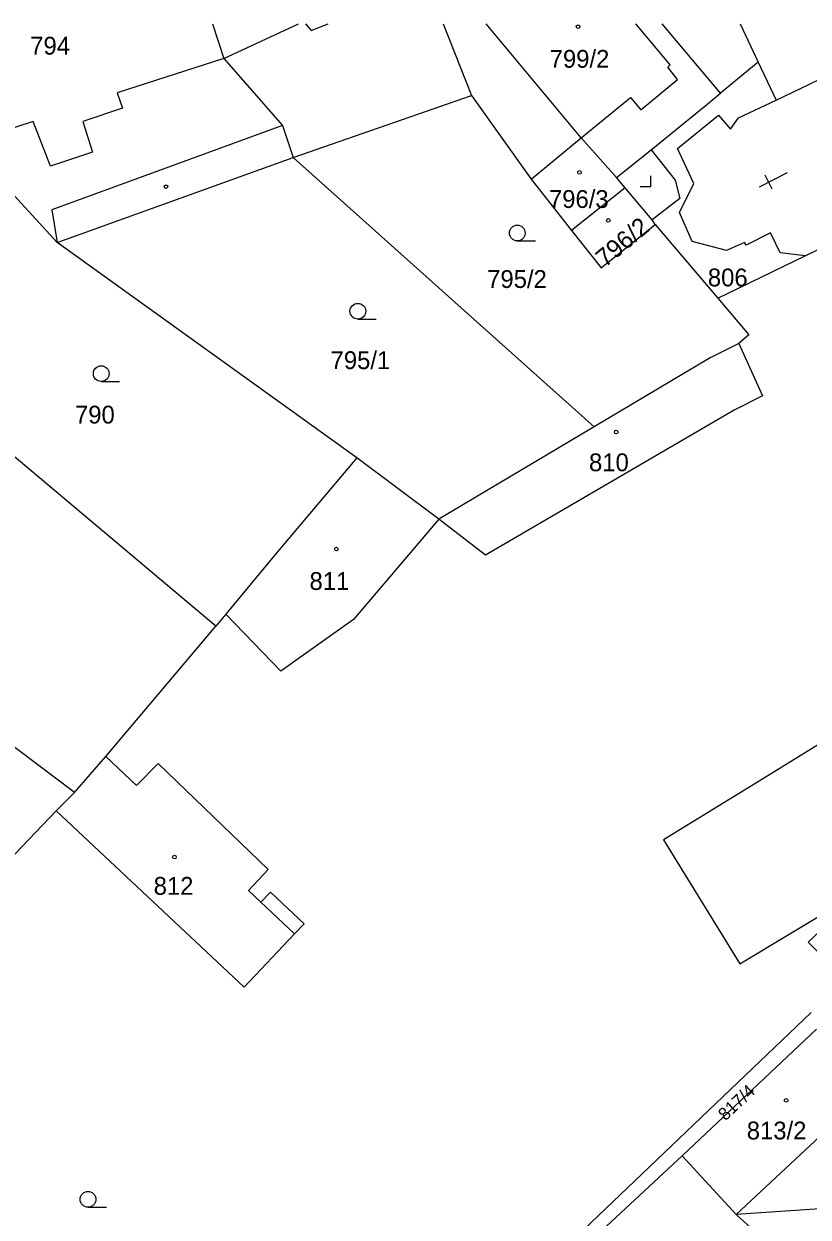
# Model space of a CAD drawing. Extents: x -496682 to -495907, y -1088575 to -1088018.
# Drawn here: x -496396.5 to -496321.7, y -1088133.3 to -1088019.5 of the extents above; entities that cross this region are included whole.
import ezdxf

# ---------------------------------------------------------------- set-up
doc = ezdxf.new("R2010")
doc.units = 0
for name, color, linetype in [('Hranice parcel', 7, 'Continuous'), ('Parcelní čísla', 7, 'Continuous'), ('Vnitřní kresba', 7, 'Continuous'), ('Značky budov', 7, 'Continuous'), ('Značky kultur', 7, 'Continuous')]:
    doc.layers.add(name, color=color, linetype=linetype)

msp = doc.modelspace()

# ---------------------------------------------------------------- linework, layer by layer
at = {"layer": 'Hranice parcel'}
for p, q in [((-496328.16, -1088019.49), (-496326.44, -1088023.13)), ((-496326.44, -1088023.13), (-496330.05, -1088026.09)), ((-496326.44, -1088023.13), (-496324.74, -1088026.75)), ((-496348.1, -1088034.29), (-496343.33, -1088030.37)), ((-496339.97, -1088034.14), (-496343.33, -1088030.37)), ((-496393.29, -1088040.33), (-496370.79, -1088032.22)), ((-496370.79, -1088032.22), (-496342.08, -1088057.91)), ((-496348.1, -1088034.29), (-496344.26, -1088039.18)), ((-496339.12, -1088035.12), (-496339.97, -1088034.14)), ((-496393.29, -1088040.33), (-496398.07, -1088035.13)), ((-496339.12, -1088035.12), (-496344.26, -1088039.18)), ((-496336.28, -1088038.61), (-496330.3, -1088045.65)), ((-496364.73, -1088060.87), (-496393.29, -1088040.33)), ((-496330.3, -1088045.65), (-496321.98, -1088041.61)), ((-496378.15, -1088076.93), (-496400.58, -1088058.06)), ((-496342.08, -1088057.91), (-496356.91, -1088066.71)), ((-496356.91, -1088066.71), (-496364.73, -1088060.87)), ((-496377.22, -1088075.77), (-496378.15, -1088076.93)), ((-496388.65, -1088089.36), (-496378.15, -1088076.93)), ((-496391.63, -1088092.77), (-496388.65, -1088089.36)), ((-496393.38, -1088094.52), (-496391.63, -1088092.77)), ((-496373.06, -1088163.12), (-496321.41, -1088113.75)), ((-496320.9, -1088115.37), (-496333.69, -1088127.43)), ((-496328.55, -1088133.03), (-496315.65, -1088120.99)), ((-496333.69, -1088127.43), (-496357.36, -1088149.42)), ((-496333.69, -1088127.43), (-496328.55, -1088133.03)), ((-496287.5, -1088130.23), (-496328.55, -1088133.03))]:
    msp.add_line(p, q, dxfattribs=at)
for points in [[(-496378.48, -1088019.49), (-496377.39, -1088022.78), (-496371.82, -1088029.18), (-496370.79, -1088032.22)], [(-496343.33, -1088030.37), (-496352.39, -1088019.49)], [(-496330.05, -1088026.09), (-496335.61, -1088019.49)], [(-496324.74, -1088026.75), (-496317.45, -1088023.28), (-496311.34, -1088021.2), (-496307.78, -1088019.49)], [(-496370.79, -1088032.22), (-496353.78, -1088026.33), (-496348.1, -1088034.29)], [(-496339.97, -1088034.14), (-496336.64, -1088031.5), (-496331.54, -1088027.32), (-496330.05, -1088026.09)], [(-496321.98, -1088041.61), (-496324.37, -1088041.31), (-496325.28, -1088039.42), (-496327.61, -1088040.59), (-496327.75, -1088040.32), (-496329.48, -1088041.1), (-496332.73, -1088040.23), (-496333.96, -1088037.46), (-496332.59, -1088034.7), (-496334.13, -1088031.37), (-496330.23, -1088028.2), (-496329.09, -1088029.54), (-496328.32, -1088028.45), (-496324.74, -1088026.75)], [(-496336.28, -1088038.61), (-496336.57, -1088038.17), (-496339.12, -1088035.12)], [(-496321.98, -1088041.61), (-496311.24, -1088036.41), (-496311.47, -1088035.95), (-496310.17, -1088035.32)], [(-496344.26, -1088039.18), (-496341.41, -1088042.74), (-496336.28, -1088038.61)], [(-496330.3, -1088045.65), (-496327.33, -1088049.15), (-496328.29, -1088049.97)], [(-496328.29, -1088049.97), (-496326.03, -1088054.97), (-496328.74, -1088056.34), (-496352.45, -1088070.14), (-496356.91, -1088066.71)], [(-496328.29, -1088049.97), (-496331.02, -1088051.35), (-496342.08, -1088057.91)], [(-496364.73, -1088060.87), (-496372.46, -1088070.06), (-496377.22, -1088075.77)], [(-496391.63, -1088092.77), (-496417.3, -1088073.45), (-496426.74, -1088064.5)], [(-496356.91, -1088066.71), (-496365.03, -1088076.3), (-496371.95, -1088081.22), (-496377.22, -1088075.77)], [(-496309.39, -1088081.23), (-496325.96, -1088091.45), (-496335.48, -1088097.3), (-496328.2, -1088109.13), (-496318.63, -1088103.36)], [(-496388.65, -1088089.36), (-496385.72, -1088092.12), (-496383.67, -1088090.01), (-496373.16, -1088100.13), (-496375.06, -1088102.13), (-496373.87, -1088103.25), (-496372.96, -1088102.28), (-496369.75, -1088105.3), (-496370.66, -1088106.26), (-496375.45, -1088111.36), (-496393.38, -1088094.52)], [(-496419.93, -1088122.62), (-496405.88, -1088107.6), (-496393.38, -1088094.52)], [(-496319.99, -1088105.46), (-496321.7, -1088107.07), (-496318.3, -1088110.48)], [(-496328.55, -1088133.03), (-496327.18, -1088134.28), (-496328.71, -1088135.71)]]:
    msp.add_lwpolyline(points, dxfattribs=at)
at = {"layer": 'Vnitřní kresba'}
for p, q in [((-496377.39, -1088022.78), (-496370.29, -1088019.49)), ((-496369.61, -1088019.49), (-496369.07, -1088020.13)), ((-496369.07, -1088020.13), (-496367.46, -1088019.49)), ((-496356.49, -1088019.49), (-496353.78, -1088026.33)), ((-496334.85, -1088023.38), (-496338.12, -1088019.49)), ((-496377.39, -1088022.78), (-496387.56, -1088026.07)), ((-496335.08, -1088023.62), (-496334.85, -1088023.38)), ((-496334.13, -1088024.78), (-496335.08, -1088023.62)), ((-496337.64, -1088027.69), (-496334.13, -1088024.78)), ((-496387.56, -1088026.07), (-496387.06, -1088027.53)), ((-496343.33, -1088030.37), (-496338.62, -1088026.5)), ((-496338.62, -1088026.5), (-496337.64, -1088027.69)), ((-496387.06, -1088027.53), (-496390.85, -1088028.8)), ((-496395.59, -1088028.81), (-496402.96, -1088031.19)), ((-496393.92, -1088033.06), (-496395.59, -1088028.81)), ((-496390.85, -1088028.8), (-496389.93, -1088031.72)), ((-496371.82, -1088029.18), (-496393.79, -1088037.22)), ((-496389.93, -1088031.72), (-496393.92, -1088033.06)), ((-496336.64, -1088031.5), (-496334.36, -1088034.39)), ((-496334.36, -1088034.39), (-496333.93, -1088036.13)), ((-496333.93, -1088036.13), (-496336.57, -1088038.17)), ((-496393.79, -1088037.22), (-496393.29, -1088040.33)), ((-496373.87, -1088103.25), (-496370.66, -1088106.26))]:
    msp.add_line(p, q, dxfattribs=at)
at = {"layer": 'Značky budov'}
for p, q in [((-496326.34, -1088035.02), (-496323.67, -1088033.66)), ((-496325.11, -1088035.24), (-496325.79, -1088033.9))]:
    msp.add_line(p, q, dxfattribs=at)
for centre in [(-496343.62, -1088019.75), (-496343.5, -1088033.65), (-496382.91, -1088035.01), (-496340.74, -1088038.23), (-496339.99, -1088058.42), (-496366.67, -1088069.58), (-496382.11, -1088098.95), (-496323.79, -1088122.15)]:
    msp.add_circle(centre, 0.175, dxfattribs=at)
at = {"layer": 'Značky kultur'}
for p, q in [((-496336.7, -1088034.99), (-496336.7, -1088033.99)), ((-496337.7, -1088034.99), (-496336.7, -1088034.99)), ((-496349.42, -1088040.18), (-496347.67, -1088040.18)), ((-496364.62, -1088047.64), (-496362.87, -1088047.64)), ((-496389.09, -1088053.59), (-496387.34, -1088053.59)), ((-496390.35, -1088132.33), (-496388.6, -1088132.33))]:
    msp.add_line(p, q, dxfattribs=at)
for centre in [(-496349.42, -1088039.43), (-496364.62, -1088046.89), (-496389.09, -1088052.84), (-496390.35, -1088131.58)]:
    msp.add_circle(centre, 0.75, dxfattribs=at)

# ---------------------------------------------------------------- texts
at = {"layer": 'Parcelní čísla'}
for s, p in [('794', (-496395.86, -1088022.42)), ('799/2', (-496346.33, -1088023.67)), ('796/3', (-496346.4, -1088037.04)), ('795/2', (-496352.29, -1088044.67)), ('806', (-496331.25, -1088044.52)), ('795/1', (-496367.22, -1088052.41)), ('790', (-496391.59, -1088057.6)), ('810', (-496342.58, -1088062.15)), ('811', (-496369.23, -1088073.47)), ('812', (-496384.09, -1088102.54)), ('813/2', (-496327.54, -1088125.87))]:
    msp.add_text(s, height=1.7, dxfattribs=at).set_placement(p)
for s, height, rotation, p in [('796/2', 1.7, 40, (-496341.04, -1088042.76)), ('817/4', 1.2, 43, (-496329.58, -1088124.15))]:
    msp.add_text(s, height=height, rotation=rotation, dxfattribs=at).set_placement(p)

doc.saveas('drawing.dxf')
